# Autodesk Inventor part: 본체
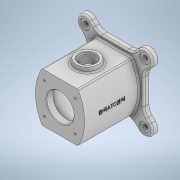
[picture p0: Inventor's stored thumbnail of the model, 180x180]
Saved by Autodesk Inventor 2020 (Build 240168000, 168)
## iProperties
Created: 2022-01
Part Number: 본체
Material: 일반
Document SubType Name: Modeling
Designer: user
Density: 1 g/cm^3
Appearance: 기본값
Mass: 459.178 g
Surface Area: 908.253 cm^2
Volume: 459.178 cm^3
Author: user
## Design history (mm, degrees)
sketch "스케치1"
  geometry: L1 (-32.942, 45)-(32.942, 45); L2 (32.942, -45)-(-32.942, -45); L3 (-45, 45)-(45, -45); L4 (45, 45)-(-45, -45); A1 r 90 centre (45, 0) between (-32.942, 45) and (-32.942, -45); A2 r 90 centre (-45, 0) between (32.942, -45) and (32.942, 45); 2 further points
  constraints: 8 end point, 6 point on circle, 2 centre point, 2 midpoint, 2 vertical alignment, 1 horizontal, 1 parallel, 1 perpendicular
  dimensions: "d0" = 90 distance of L3.end L4.end; "d1" = 90 distance of L4.start L3.end; "d2" = 90 radius of A1; "d3" = 90 radius of A2; "d4" = 45 deg angle of L3 L1; "d5" = 90 distance between parallel lines of L2 L1; "d6" = 45 distance from line of point (0, 0) L1; "d7" = 0 distance from line of L4.start L1; "d8" = 31.81981 distance from line of A1.centre L3; "d9" = 0 distance from line of L3.start L1
extrude "돌출1" new body sketch "스케치1" distance "d10" = 100; taper "d11" = 0 deg
sketch "스케치2"
  geometry: L1 (53, 53)-(-53, 53); L2 (-53, 53)-(-53, -53); L3 (-53, -53)-(53, -53); L4 (53, -53)-(53, 53); L5 (-54.447, -54.447)-(54.447, 54.447); L6 (-43.841, -65.054)-(65.054, 43.841); L7 (43.841, 65.054)-(-65.054, -43.841); L8 (54.447, -54.447)-(-54.447, 54.447); L9 (65.054, -43.841)-(-43.841, 65.054); L10 (-65.054, 43.841)-(43.841, -65.054); A1 r 15 centre (-54.447, -54.447) between (-65.054, -43.841) and (-43.841, -65.054); A2 r 15 centre (54.447, 54.447) between (65.054, 43.841) and (43.841, 65.054); A3 r 15 centre (54.447, -54.447) between (43.841, -65.054) and (65.054, -43.841); A4 r 15 centre (-54.447, 54.447) between (-43.841, 65.054) and (-65.054, 43.841); 11 further points
  constraints: 24 end point, 8 point on circle, 8 tangent, 4 centre point, 4 midpoint, 4 parallel, 1 horizontal, 1 horizontal alignment, 1 perpendicular, 1 vertical alignment
  dimensions: "d12" = 106 distance of L3.end L2.end; "d13" = 106 distance of L2.end L1.end; "d81" = 45 deg angle of L8 L3; "d82" = 45 deg angle of L5 L3; "d83" = 154 distance of L8.start L8.end; "d84" = 154 distance of L5.end L5.start; "d85" = 30 distance between parallel lines of L6 L7; "d86" = 30 distance between parallel lines of L10 L9
sketch "스케치3"
  geometry: C1 r 25 at (0, 0); 1 further point
  constraints: 1 centre point, 1 coincident
  dimensions: "d19" = 50 diameter of C1
extrude "돌출3" cut sketch "스케치3" distance "d20" = 12; taper "d21" = 0 deg
sketch "스케치4"
  geometry: C1 r 37 at (0, 0); 1 further point
  constraints: 1 centre point, 1 coincident
  dimensions: "d22" = 74 diameter of C1
extrude "돌출4" cut sketch "스케치4" distance "d23" = 86; taper "d24" = 0 deg
sketch "스케치5"
  geometry: C1 r 25 at (0, 0); 1 further point
  constraints: 1 centre point, 1 coincident
  dimensions: "d25" = 50 diameter of C1
extrude "돌출5" cut sketch "스케치5" distance "d26" = 12; taper "d27" = 0 deg
node "작업 평면1"
sketch "스케치6"
  geometry: L1 (53, -10)-(-53, -10) reference; L2 (53, 0)-(-53, 0) reference; C1 r 20 at (0, 50); 6 further points
  constraints: 1 centre point, 1 midpoint, 1 vertical alignment
  dimensions: "d29" = 60 distance from line of L1 C1.centre; "d30" = 40 diameter of C1
extrude "돌출6" join sketch "스케치6" stored distance "d31" = 12; taper "d32" = 15 deg
sketch "스케치7"
  geometry: C1 r 20 at (0, 0) reference; C2 r 15 at (0, 0); 1 further point
  constraints: 1 centre point, 1 coincident
  dimensions: "d33" = 30 diameter of C2
extrude "돌출7" cut sketch "스케치7" distance "d34" = 5; taper "d35" = 0 deg
sketch "스케치8"
  geometry: C1 r 15 at (0, 0) reference; C2 r 12 at (0, 0); 1 further point
  constraints: 1 centre point, 1 coincident
  dimensions: "d36" = 24 diameter of C2
extrude "돌출8" cut sketch "스케치8" stored distance "d37" = 5; taper "d38" = 0 deg
sketch "스케치9" dims "d39" = 80
  geometry: L1 (0, 0)-(-10.788, 0); 5 further points
  constraints: 2 end point, 2 symmetric about line, 1 coincident, 1 horizontal, 3 other
hole "구멍1" sketch "스케치9" at (28.284, 28.284), (-28.284, 28.284), (-28.284, -28.284), (28.284, -28.284) diameter "d41" = 3.242; stored, may be unused: countersink angle "d45" = 90 deg, drill point angle "d47" = 118 deg; dims "d42" = 8, "d43" = 4, "d44" = 2, "d46" = 10
node "작업 평면4"
sketch "스케치10"
  geometry: L1 (0, 0)-(-13.388, 0); C1 r 40 at (0, 0); C2 r 1.621 at (28.284, 28.284) reference; 5 further points
  constraints: 2 coincident, 2 end point, 2 symmetric about line, 1 centre point, 1 horizontal
  dimensions: "d48" = 80 diameter of C1
hole "구멍2" sketch "스케치10" at (28.284, 28.284), (-28.284, 28.284), (-28.284, -28.284), (28.284, -28.284) diameter "d50" = 3.242; stored, may be unused: countersink angle "d54" = 90 deg, drill point angle "d56" = 118 deg; dims "d51" = 8, "d52" = 4, "d53" = 2, "d55" = 10
node "작업 평면3"
sketch "스케치11" dims "d57" = 154
  geometry: L1 (0, 0)-(-75.76, 75.76); L2 (0, 0)-(0, 97.42); L3 (0, 0)-(11.845, 0); C1 r 9 at (-54.447, 54.447); C2 r 9 at (54.447, 54.447); C3 r 9 at (-54.447, -54.447); C4 r 9 at (54.447, -54.447); 1 further point
  constraints: 6 end point, 4 centre point, 3 symmetric about line, 1 coincident, 1 horizontal, 1 point on line, 1 vertical, 6 other
  dimensions: "d58" = 45 deg angle of L1 L2; "d59" = 18 diameter of C1
extrude "돌출9" cut sketch "스케치11" distance "d60" = 2; taper "d61" = 0 deg
node "작업 평면2"
sketch "스케치12"
  geometry: C1 r 4.5 at (-54.447, 54.447); C2 r 4.5 at (-54.447, -54.447); C3 r 4.5 at (54.447, -54.447); C4 r 4.5 at (54.447, 54.447); A1 r 9 centre (-54.447, 54.447) between (-53, 45.564) and (-45.564, 53) reference; A2 r 9 centre (54.447, 54.447) between (45.564, 53) and (53, 45.564) reference; A3 r 9 centre (54.447, -54.447) between (53, -45.564) and (45.564, -53) reference; A4 r 9 centre (-54.447, -54.447) between (-45.564, -53) and (-53, -45.564) reference; 1 further point
  constraints: 4 centre point, 4 coincident
  dimensions: "d62" = 9 diameter of C1; "d63" = 9 diameter of C2; "d64" = 9 diameter of C3; "d65" = 9 diameter of C4
extrude "돌출10" cut sketch "스케치12" extent not by distance; stored distance "d66" = 0; taper "d67" = 0 deg
sketch "스케치13" dims "d0" = 90, "d1" = 90, "d2" = 90, "d3" = 90, "d4" = 45 deg, "d5" = 90, "d6" = 45, "d7" = 0, "d8" = 31.81981, "d9" = 0, "d19" = 50
  geometry: L1 (25, -10)-(-25, -10) reference; L2 (53, 30)-(53, 70) reference; 2 further points
  constraints: 1 other
  dimensions: "d69" = 60 distance from line of L1 point (0, 50); "d70" = 53 distance from line of L2 point (0, 50)
feature "엠보싱1" sketch "스케치13" dims "d71" = 0.5, "d72" = 0
chamfer "모따기1" distance "d73" = 1; stored, may be unused: second distance "d74" = 2, angle "d75" = 45 deg
fillet "모깎기2" dims "d76" = 3
fillet "모깎기4" dims "d78" = 3
fillet "모깎기5" dims "d79" = 3
extrude "돌출11" join sketch "스케치2" distance "d87" = 10; taper "d88" = 0 deg
sketch "스케치14"
  geometry: C1 r 9 at (-54.447, 54.447); C2 r 9 at (54.447, 54.447); C3 r 9 at (54.447, -54.447); C4 r 9 at (-54.447, -54.447); A1 r 15 centre (-54.447, 54.447) between (-43.841, 65.054) and (-65.054, 43.841) reference; A2 r 15 centre (54.447, 54.447) between (65.054, 43.841) and (43.841, 65.054) reference; A3 r 15 centre (54.447, -54.447) between (43.841, -65.054) and (65.054, -43.841) reference; A4 r 15 centre (-54.447, -54.447) between (-65.054, -43.841) and (-43.841, -65.054) reference; 1 further point
  constraints: 4 centre point, 4 coincident
  dimensions: "d90" = 18 diameter of C1; "d91" = 18 diameter of C2; "d92" = 18 diameter of C3; "d93" = 18 diameter of C4
extrude "돌출12" cut sketch "스케치14" distance "d94" = 2; taper "d95" = 0 deg
sketch "스케치15"
  geometry: C1 r 9 at (-54.447, 54.447) reference; C2 r 9 at (54.447, 54.447) reference; C3 r 9 at (54.447, -54.447) reference; C4 r 9 at (-54.447, -54.447) reference; C5 r 4.5 at (-54.447, 54.447); C6 r 4.5 at (54.447, 54.447); C7 r 4.5 at (54.447, -54.447); C8 r 9 at (-54.447, -54.447) reference; C9 r 4.5 at (-54.447, -54.447); 1 further point
  constraints: 4 centre point, 4 coincident
  dimensions: "d96" = 9 diameter of C5; "d97" = 9 diameter of C6; "d98" = 9 diameter of C7; "d99" = 9 diameter of C9
extrude "돌출13" cut sketch "스케치15" extent not by distance; stored distance "d100" = 0; taper "d101" = 0 deg
sketch "스케치16"
  geometry: C1 r 25 at (0, 0); 1 further point
  constraints: 1 centre point, 1 coincident
  dimensions: "d102" = 50 diameter of C1
extrude "돌출14" cut sketch "스케치16" distance "d103" = 12; taper "d104" = 0 deg
fillet "모깎기7" dims "d105" = 20
sketch "스케치17"
  geometry: L1 (0, 0)-(0, 78.13); L2 (0, 0)-(69.361, 69.361); L3 (0, 0)-(-11.347, 0); C1 r 40 at (0, 0); C2 r 1.621 at (28.284, 28.284) reference; 4 further points
  constraints: 6 end point, 3 symmetric about line, 2 coincident, 1 centre point, 1 horizontal, 1 vertical
  dimensions: "d106" = 80 diameter of C1; "d107" = 45 deg angle of L2 L1
hole "구멍3" sketch "스케치17" at (28.284, 28.284), (-28.284, 28.284), (-28.284, -28.284), (28.284, -28.284) diameter "d108" = 3.242; stored, may be unused: countersink angle "d112" = 90 deg, drill point angle "d114" = 118 deg; dims "d109" = 8, "d110" = 4, "d111" = 2, "d113" = 10
fillet "모깎기8" dims "d115" = 3
chamfer "모따기2" distance "d116" = 1; stored, may be unused: second distance "d117" = 2, angle "d118" = 45 deg
node "솔리드1"
node "투영된 루프1"
node "투영된 루프2"
node "투영된 루프3"
feature "A9D066F2-1C7D-4E18-AEED-F7BC21143FA4" dims "d41" = 3.242, "d42" = 8, "d43" = 4, "d44" = 2, "d45" = 90 deg, "d46" = 10, "d47" = 118 deg
other parameters: "d28" = 53
